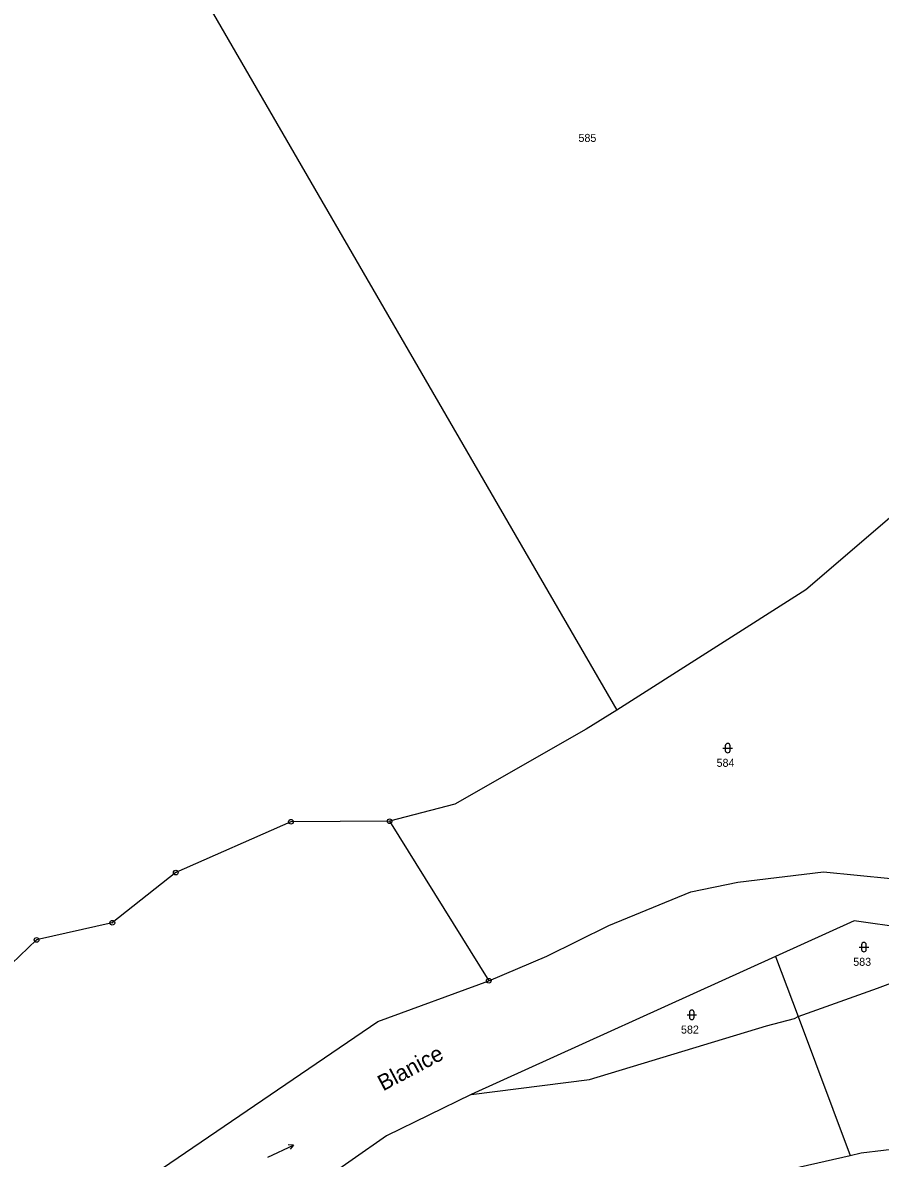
# Model space of a CAD drawing. Extents: x -719614 to -717765, y -1095834 to -1093862.
# Drawn here: x -718549.9 to -718367.7, y -1095270.4 to -1095029.2 of the extents above; entities that cross this region are included whole.
import ezdxf
from ezdxf.enums import TextEntityAlignment as Align

# ---------------------------------------------------------------- set-up
doc = ezdxf.new("R2010")
doc.units = 0
doc.header["$LTSCALE"] = 0.68
for name, color, linetype, lineweight in [('1', 7, 'Continuous', 25), ('3', 7, 'Continuous', 25), ('8', 7, 'Continuous', 25)]:
    doc.layers.add(name, color=color, linetype=linetype, lineweight=lineweight)
doc.layers.add('2', color=7, linetype='Continuous')
doc.layers.add('7', color=7, linetype='Continuous')

msp = doc.modelspace()

# ---------------------------------------------------------------- linework, layer by layer
at = {"layer": '1'}
for p, q in [((-718536.12, -1094981.15), (-718446.03, -1095136.65)), ((-718356.19, -1095126.27), (-718383.53, -1095149.71)), ((-718446.03, -1095136.65), (-718423.69, -1095175.21)), ((-718383.53, -1095149.71), (-718423.69, -1095175.21)), ((-718423.69, -1095175.21), (-718430.16, -1095179.31)), ((-718430.16, -1095179.31), (-718458.06, -1095195.17)), ((-718458.06, -1095195.17), (-718471.93, -1095198.83)), ((-718492.89, -1095198.93), (-718517.35, -1095209.74)), ((-718471.93, -1095198.83), (-718492.89, -1095198.93)), ((-718471.93, -1095198.83), (-718450.87, -1095232.7)), ((-718517.35, -1095209.74), (-718530.84, -1095220.4)), ((-718397.99, -1095211.8), (-718379.75, -1095209.59)), ((-718379.75, -1095209.59), (-718365.49, -1095210.98)), ((-718407.93, -1095213.82), (-718397.99, -1095211.8)), ((-718425.4, -1095220.96), (-718407.93, -1095213.82)), ((-718530.84, -1095220.4), (-718546.92, -1095224.03)), ((-718438.51, -1095227.46), (-718425.4, -1095220.96)), ((-718373.27, -1095219.99), (-718389.94, -1095227.54)), ((-718359.39, -1095221.98), (-718373.27, -1095219.99)), ((-718546.92, -1095224.03), (-718554, -1095230.84)), ((-718389.94, -1095227.54), (-718454.6, -1095256.83)), ((-718450.87, -1095232.7), (-718438.51, -1095227.46)), ((-718389.94, -1095227.54), (-718385.17, -1095240.31)), ((-718368.3, -1095234.29), (-718354.36, -1095228.91)), ((-718474.41, -1095241.35), (-718450.87, -1095232.7)), ((-718385.17, -1095240.31), (-718368.3, -1095234.29)), ((-718528.56, -1095278.15), (-718474.41, -1095241.35)), ((-718391.88, -1095242.3), (-718385.89, -1095240.69)), ((-718385.89, -1095240.69), (-718385.17, -1095240.31)), ((-718385.17, -1095240.31), (-718374.13, -1095269.82)), ((-718429.5, -1095253.69), (-718391.88, -1095242.3)), ((-718454.6, -1095256.83), (-718429.5, -1095253.69)), ((-718454.6, -1095256.83), (-718472.63, -1095265.67)), ((-718472.63, -1095265.67), (-718489.02, -1095277.08)), ((-718371.73, -1095269.28), (-718357.59, -1095267.53)), ((-718418.73, -1095279.86), (-718374.13, -1095269.82)), ((-718374.13, -1095269.82), (-718371.73, -1095269.28))]:
    msp.add_line(p, q, dxfattribs=at)
at = {"layer": '3'}
for p, q in [((-718401.121, -1095183.291), (-718399.119, -1095183.291)), ((-718400.621, -1095182.791), (-718400.621, -1095183.792)), ((-718399.619, -1095183.792), (-718399.619, -1095182.791)), ((-718372.171, -1095225.551), (-718370.169, -1095225.551)), ((-718371.671, -1095225.051), (-718371.671, -1095226.052)), ((-718370.669, -1095226.052), (-718370.669, -1095225.051)), ((-718408.741, -1095239.941), (-718406.739, -1095239.941)), ((-718408.241, -1095239.441), (-718408.241, -1095240.442)), ((-718407.239, -1095240.442), (-718407.239, -1095239.441)), ((-718492.372, -1095267.603), (-718493.046, -1095268.47))]:
    msp.add_line(p, q, dxfattribs=at)
msp.add_lwpolyline([(-718497.81, -1095270.138), (-718492.372, -1095267.603), (-718493.469, -1095267.561)], dxfattribs=at)
for centre, start, end in [((-718400.12, -1095182.7909), 0, 180), ((-718400.12, -1095183.7909), 180, 359.98789), ((-718371.17, -1095225.0509), 0, 180), ((-718371.17, -1095226.0509), 180, 359.98789), ((-718407.74, -1095239.4409), 0, 180), ((-718407.74, -1095240.4409), 180, 359.98789)]:
    msp.add_arc(centre, 0.5, start, end, dxfattribs=at)
at = {"layer": '8'}
for centre, radius in [((-718492.89, -1095198.9299), 0.5), ((-718492.89, -1095198.9299), 0.0303), ((-718471.93, -1095198.8299), 0.5), ((-718471.93, -1095198.8299), 0.0303), ((-718517.35, -1095209.7399), 0.5), ((-718517.35, -1095209.7399), 0.0303), ((-718530.84, -1095220.3999), 0.5), ((-718530.84, -1095220.3999), 0.0303), ((-718546.92, -1095224.0299), 0.5), ((-718546.92, -1095224.0299), 0.0303), ((-718450.87, -1095232.6999), 0.5), ((-718450.87, -1095232.6999), 0.0303)]:
    msp.add_circle(centre, radius, dxfattribs=at)

# ---------------------------------------------------------------- texts
at = {"layer": '2'}
for s, p in [('585', (-718429.919, -1095054.562)), ('584', (-718400.579, -1095187.272)), ('583', (-718371.549, -1095229.532)), ('582', (-718408.139, -1095243.922))]:
    msp.add_text(s, height=1.7, dxfattribs=at).set_placement(p, align=Align.CENTER)
at = {"layer": '7'}
msp.add_text('Blanice', height=3.4, rotation=28, dxfattribs=at).set_placement((-718466.7346, -1095252.7145), align=Align.CENTER)

doc.saveas('drawing.dxf')
